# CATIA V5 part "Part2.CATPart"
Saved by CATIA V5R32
Part number: Part2
Bounding box of the stored display mesh (mm): x 0 to 20, y -69.015 to 69.015, z 7.835 to 66.136
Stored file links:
  D:\PROJECTS\Project 2022\CATIA V5 6R 2022\Resources\Part Files\c16_catia_v5_6r2022_prt\Slide Curve Joint-(Fig16-40)\Part2.CATPart
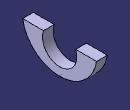
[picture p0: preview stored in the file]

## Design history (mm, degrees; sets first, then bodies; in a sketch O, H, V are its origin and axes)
Body1 (main body)
  Sketch1 on yz-plane, origin (0, 0, 0), H (0, 1, 0), V (0, 0, 1)
    arc A1 centre (0, 77.8354) radius 70 from (-69.0153, 66.1355) to (69.0153, 66.1355) ccw
    point P1 (0, 77.8354)
    point P2 (-69.0153, 66.1355)
    point P3 (69.0153, 66.1355)
    arc A2 centre (0, 55) radius 32 from (-30, 66.1355) to (30, 66.1355) ccw
    point P4 (0, 55)
    point P5 (-30, 66.1355)
    point P6 (30, 66.1355)
    line L1 (30, 66.1355) -> (69.0153, 66.1355)
    point P7 (69.0153, 66.1355)
    line L2 (-30, 66.1355) -> (-69.0153, 66.1355)
    point P8 (-69.0153, 66.1355)
    reference intersected line E1 through (0, 0) direction (-1, 0) from xy-plane
    reference intersected line E3 through (0, 0) direction (0, 1) from zx-plane
    radius A1 = 70
    radius A2 = 32
    distance P6 P7 = 39.0153
    distance P6 E3 = 30
    distance P4 H = 55
    coincidence: P1 V, P4 V, P7 P3, P8 A1, P2 P8, L2 L1, E3 P1, P2 L1, P3 L1, P5 L1, P6 L2
    horizontal: L1 H, L2 H, E1 H
    vertical: E3 V
    perpendicularity: E3 L1
  Pad1: profile Sketch1, direction (1, 0, 0), length 20
  Point1: type OnCurve, Support edge [face of Pad1 from Sketch1.A1 | end face of Pad1], Ratio 0.5
  Sketch2 on yz-plane, origin (0, 0, 0), H (0, 1, 0), V (0, 0, 1)
    line L1 (0, 81.1355) -> (0, 51.1355)
    point P1 (0, 81.1355)
    reference projected line E1 (69.0153, 66.1355) -> (30, 66.1355) from edge [face of Pad1 from Sketch1.L1 | end face of Pad1]
    length L1 = 30
    distance E1 P1 = 15
    coincidence: P1 V
    vertical: L1 V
